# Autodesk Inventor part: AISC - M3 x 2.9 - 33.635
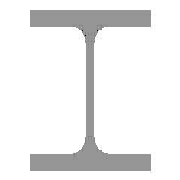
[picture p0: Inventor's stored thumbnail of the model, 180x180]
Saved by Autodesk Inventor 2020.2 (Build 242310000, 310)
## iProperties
_CCFamilyMember: 14
_CCFamilyDisplayName: ANSI M - M-Shape — Sizes in parentheses have been withdrawn
_FrameMemberDoc: Frame Member File
_Version: 15.0.0
_GetPNFromCC: 1
Created: 2020-01
Part Number: AISC - M3 x 2.9 - 33.635
Material: Steel, Mild
Description: M-Shape
Document SubType Name: Modeling
Standard: ANSI
Designer: thira
Standards Organization: ANSI
Language: en-US
Size Designation: M3 x 2.9
Categories: <MemberInstance><Categories><Category DisplayName="Structural Shapes" InternalName="089c4875-fa83-4c05-b084-43b9cc11f5ed" Mnemonic="GRDR"><CategoryParameter Dis
Stock Number: M3 x 2.9
Density: 7.85 g/cm^3
Appearance: Semi-Polished
G_L: 33.635 in
G_W: 2.250 in
G_H: 3.000 in
+F925D24F-D68D-4F5E-A87D-887464E8C1D5+CUTDETAIL1: Miter 45.00 deg
+5A0D731E-022E-4378-A517-99784A717457+CUTDETAIL2: Miter 45.00 deg
IsCustomPart: 1
Author: thira
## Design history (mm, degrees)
node "Start Plane"
node "End Plane"
sketch "Sketch"
  geometry: L1 (-28.575, -38.1)-(-28.575, -34.798); L2 (-28.575, -34.798)-(-10.541, -34.798); L3 (-1.143, -25.4)-(-1.143, 0); L4 (-1.143, 0)-(0, 0); L5 (0, 0)-(0, -38.1); L6 (0, -38.1)-(-28.575, -38.1); L7 (-60, 0)-(80, 0); L8 (0, -60)-(0, 80); L9 (28.575, -38.1)-(28.575, -34.798); L10 (28.575, -34.798)-(10.541, -34.798); L11 (0, -38.1)-(28.575, -38.1); L12 (1.143, -25.4)-(1.143, 0); L13 (1.143, 0)-(0, 0); L14 (-28.575, 38.1)-(-28.575, 34.798); L15 (0, 38.1)-(-28.575, 38.1); L16 (0, 38.1)-(28.575, 38.1); L17 (28.575, 34.798)-(10.541, 34.798); L18 (-28.575, 34.798)-(-10.541, 34.798); L19 (1.143, 25.4)-(1.143, 0); L20 (-1.143, 25.4)-(-1.143, 0); L21 (28.575, 38.1)-(28.575, 34.798); L22 (0, 108)-(0, -88) reference; L23 (-88, 0)-(108, 0) reference; A1 r 9.398 centre (-10.541, 25.4) between (-1.143, 25.4) and (-10.541, 34.798); A2 r 9.398 centre (10.541, 25.4) between (10.541, 34.798) and (1.143, 25.4); A3 r 9.398 centre (10.541, -25.4) between (1.143, -25.4) and (10.541, -34.798); A4 r 9.398 centre (-10.541, -25.4) between (-10.541, -34.798) and (-1.143, -25.4); 4 further points
  constraints: 42 end point, 11 symmetric about line, 8 point on circle, 8 point on line, 8 tangent, 4 centre point, 4 collinear, 4 parallel, 3 equal radius, 1 perpendicular, 1 vertical, 13 other
  dimensions: "d1" = 38.1 vertical distance of L1.start L3.end (= 0.5 x G_H); "d2" = 3.302 distance between parallel lines of L2 L6 (= G_T1); "d3" = 28.575 distance from line of L5.end L1 (= 0.5 x G_W); "d4" = 1.143 distance between parallel lines of L5 L3 (= 0.5 x G_T); "d13" = 9.398 radius of A1 (= G_IR)
extrude "Body" new body sketch "Sketch" stored distance "d5" = 854.32157 (= G_L); taper "d6" = 0 deg
node "Driven Length"
  sketch "Sketch4"
    geometry: L1 (0, 0)-(10, 0) reference
    constraints: 2 end point, 1 horizontal
  workplane "Work Plane3"
  sketch "Sketch5"
    geometry: L1 (-2, -27.161)-(12, -27.161) reference; L2 (-2, 827.161)-(12, 827.161) reference
    dimensions: "d15" = 854.32157 distance between parallel lines of L1 L2 (derived)
workplane "Work Plane4"
split "Split1"
workplane "Work Plane5"
split "Split2"
body "Solid1"
other parameters: "G_W" = 57.15 [user parameter; used in 1 equation term], "G_H" = 76.2 [user parameter; used in 1 equation term], "G_T" = 2.286 [user parameter; used in 1 equation term], "G_T1" = 3.302 [user parameter; used in 1 equation term], "G_IR" = 9.398 [user parameter; used in 1 equation term], "G_L" = 854.32157 (= d15) [user parameter; used in 1 equation term], "G_OFFSET_START" = 27.16079 [user parameter; used in 1 equation term], "G_OFFSET_END" = 27.16079 [user parameter; used in 1 equation term], "d11" = -27.16079 (= -G_OFFSET_START), "d12" = 827.16079 (= G_OFFSET_END + B_L), "B_L" = 800 [user parameter; used in 1 equation term], "d14" = 90 deg
